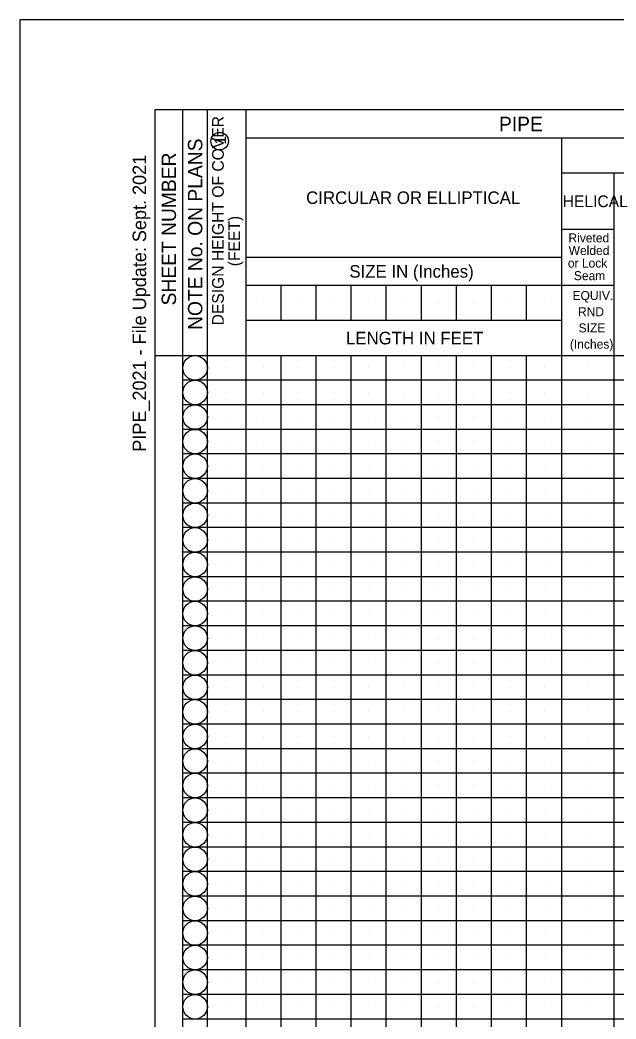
# Model space of a CAD drawing. Extents: x 0 to 1.42, y 0 to 0.92.
# Drawn here: x 0 to 0.2763, y 0.4539 to 0.9167 of the extents above; entities that cross this region are included whole.
import ezdxf

# ---------------------------------------------------------------- set-up
doc = ezdxf.new("R2010")
doc.units = 0
for name, color, linetype in [('#plot_shape', 7, 'Continuous'), ('P_ODOT_PLAN_Border', 7, 'Continuous'), ('P_ODOT_PLAN_General', 7, 'Continuous'), ('P_RDWY_PLAN_NotesTx', 7, 'Continuous')]:
    doc.layers.add(name, color=color, linetype=linetype)

msp = doc.modelspace()

# ---------------------------------------------------------------- linework, layer by layer
at = {"layer": '#plot_shape'}
msp.add_lwpolyline([(0, 0), (1.41667, 0), (1.41667, 0.91667), (0, 0.91667)], close=True, dxfattribs=at)
at = {"layer": 'P_ODOT_PLAN_Border'}
msp.add_lwpolyline([(0.0625, 0.04167), (1.39583, 0.04167), (1.39583, 0.875), (0.0625, 0.875)], close=True, dxfattribs=at)
at = {"layer": 'P_ODOT_PLAN_General'}
for p, q in [((0.07551, 0.26037), (0.07551, 0.875)), ((0.08689, 0.26037), (0.08689, 0.875)), ((0.10478, 0.26037), (0.10478, 0.875)), ((0.35681, 0.86199), (0.10478, 0.86199)), ((0.25112, 0.26037), (0.25112, 0.86199)), ((0.35681, 0.84573), (0.25112, 0.84573)), ((0.27551, 0.26037), (0.27551, 0.84573)), ((0.25112, 0.81972), (0.27551, 0.81972)), ((0.25112, 0.80671), (0.10478, 0.80671)), ((0.27551, 0.7937), (0.10478, 0.7937)), ((0.12104, 0.77744), (0.12104, 0.7937)), ((0.1373, 0.77744), (0.1373, 0.7937)), ((0.15356, 0.77744), (0.15356, 0.7937)), ((0.16982, 0.77744), (0.16982, 0.7937)), ((0.18608, 0.77744), (0.18608, 0.7937)), ((0.20234, 0.77744), (0.20234, 0.7937)), ((0.2186, 0.77744), (0.2186, 0.7937)), ((0.23486, 0.77744), (0.23486, 0.7937)), ((0.11291, 0.78557), (0.11291, 0.78557)), ((0.12917, 0.78557), (0.12917, 0.78557)), ((0.14543, 0.78557), (0.14543, 0.78557)), ((0.16169, 0.78557), (0.16169, 0.78557)), ((0.17795, 0.78557), (0.17795, 0.78557)), ((0.19421, 0.78557), (0.19421, 0.78557)), ((0.21047, 0.78557), (0.21047, 0.78557)), ((0.22673, 0.78557), (0.22673, 0.78557)), ((0.24299, 0.78557), (0.24299, 0.78557)), ((0.25112, 0.77744), (0.10478, 0.77744)), ((0.0625, 0.76118), (0.35681, 0.76118)), ((0.12104, 0.26037), (0.12104, 0.76118)), ((0.1373, 0.26037), (0.1373, 0.76118)), ((0.15356, 0.26037), (0.15356, 0.76118)), ((0.16982, 0.26037), (0.16982, 0.76118)), ((0.18608, 0.26037), (0.18608, 0.76118)), ((0.20234, 0.26037), (0.20234, 0.76118)), ((0.2186, 0.26037), (0.2186, 0.76118)), ((0.23486, 0.26037), (0.23486, 0.76118)), ((0.09583, 0.75549), (0.09583, 0.75549)), ((0.11291, 0.75549), (0.11291, 0.75549)), ((0.12917, 0.75549), (0.12917, 0.75549)), ((0.14543, 0.75549), (0.14543, 0.75549)), ((0.16176, 0.75562), (0.16176, 0.75562)), ((0.17795, 0.75549), (0.17795, 0.75549)), ((0.19421, 0.75549), (0.19421, 0.75549)), ((0.21047, 0.75549), (0.21047, 0.75549)), ((0.22673, 0.75549), (0.22673, 0.75549)), ((0.24299, 0.75549), (0.24299, 0.75549)), ((0.26331, 0.75549), (0.26331, 0.75549)), ((0.25112, 0.7498), (0.07551, 0.7498)), ((0.50965, 0.7498), (0.25112, 0.7498)), ((0.09583, 0.74411), (0.09583, 0.74411)), ((0.11291, 0.74411), (0.11291, 0.74411)), ((0.12917, 0.74411), (0.12917, 0.74411)), ((0.14543, 0.74411), (0.14543, 0.74411)), ((0.16169, 0.74411), (0.16169, 0.74411)), ((0.17795, 0.74411), (0.17795, 0.74411)), ((0.19421, 0.74411), (0.19421, 0.74411)), ((0.21047, 0.74411), (0.21047, 0.74411)), ((0.22673, 0.74411), (0.22673, 0.74411)), ((0.24299, 0.74411), (0.24299, 0.74411)), ((0.26331, 0.74411), (0.26331, 0.74411)), ((0.25112, 0.73842), (0.07551, 0.73842)), ((0.50965, 0.73842), (0.25112, 0.73842)), ((0.09583, 0.73273), (0.09583, 0.73273)), ((0.11291, 0.73273), (0.11291, 0.73273)), ((0.12917, 0.73273), (0.12917, 0.73273)), ((0.14543, 0.73273), (0.14543, 0.73273)), ((0.16169, 0.73273), (0.16169, 0.73273)), ((0.17795, 0.73273), (0.17795, 0.73273)), ((0.19421, 0.73273), (0.19421, 0.73273)), ((0.21047, 0.73273), (0.21047, 0.73273)), ((0.22673, 0.73273), (0.22673, 0.73273)), ((0.24299, 0.73273), (0.24299, 0.73273)), ((0.26331, 0.73273), (0.26331, 0.73273)), ((0.25112, 0.72703), (0.07551, 0.72703)), ((0.50965, 0.72703), (0.25112, 0.72703)), ((0.09583, 0.72134), (0.09583, 0.72134)), ((0.11291, 0.72134), (0.11291, 0.72134)), ((0.12917, 0.72134), (0.12917, 0.72134)), ((0.14543, 0.72134), (0.14543, 0.72134)), ((0.16169, 0.72134), (0.16169, 0.72134)), ((0.17795, 0.72134), (0.17795, 0.72134)), ((0.19421, 0.72134), (0.19421, 0.72134)), ((0.21047, 0.72134), (0.21047, 0.72134)), ((0.22673, 0.72134), (0.22673, 0.72134)), ((0.24299, 0.72134), (0.24299, 0.72134)), ((0.26331, 0.72134), (0.26331, 0.72134)), ((0.25112, 0.71565), (0.07551, 0.71565)), ((0.50965, 0.71565), (0.25112, 0.71565)), ((0.09583, 0.70996), (0.09583, 0.70996)), ((0.11291, 0.70996), (0.11291, 0.70996)), ((0.12917, 0.70996), (0.12917, 0.70996)), ((0.14543, 0.70996), (0.14543, 0.70996)), ((0.16169, 0.70996), (0.16169, 0.70996)), ((0.17795, 0.70996), (0.17795, 0.70996)), ((0.19421, 0.70996), (0.19421, 0.70996)), ((0.21047, 0.70996), (0.21047, 0.70996)), ((0.22673, 0.70996), (0.22673, 0.70996)), ((0.24299, 0.70996), (0.24299, 0.70996)), ((0.26331, 0.70996), (0.26331, 0.70996)), ((0.25112, 0.70427), (0.07551, 0.70427)), ((0.50965, 0.70427), (0.25112, 0.70427)), ((0.09583, 0.69858), (0.09583, 0.69858)), ((0.11291, 0.69858), (0.11291, 0.69858)), ((0.12917, 0.69858), (0.12917, 0.69858)), ((0.14543, 0.69858), (0.14543, 0.69858)), ((0.16169, 0.69858), (0.16169, 0.69858)), ((0.17795, 0.69858), (0.17795, 0.69858)), ((0.19421, 0.69858), (0.19421, 0.69858)), ((0.21047, 0.69858), (0.21047, 0.69858)), ((0.22673, 0.69858), (0.22673, 0.69858)), ((0.24299, 0.69858), (0.24299, 0.69858)), ((0.26331, 0.69858), (0.26331, 0.69858)), ((0.25112, 0.69289), (0.07551, 0.69289)), ((0.50965, 0.69289), (0.25112, 0.69289)), ((0.09583, 0.6872), (0.09583, 0.6872)), ((0.11291, 0.6872), (0.11291, 0.6872)), ((0.12917, 0.6872), (0.12917, 0.6872)), ((0.14543, 0.6872), (0.14543, 0.6872)), ((0.16169, 0.6872), (0.16169, 0.6872)), ((0.17795, 0.6872), (0.17795, 0.6872)), ((0.19421, 0.6872), (0.19421, 0.6872)), ((0.21047, 0.6872), (0.21047, 0.6872)), ((0.22673, 0.6872), (0.22673, 0.6872)), ((0.24299, 0.6872), (0.24299, 0.6872)), ((0.26331, 0.6872), (0.26331, 0.6872)), ((0.25112, 0.68151), (0.07551, 0.68151)), ((0.50965, 0.68151), (0.25112, 0.68151)), ((0.09583, 0.67582), (0.09583, 0.67582)), ((0.11291, 0.67582), (0.11291, 0.67582)), ((0.12917, 0.67582), (0.12917, 0.67582)), ((0.14543, 0.67582), (0.14543, 0.67582)), ((0.16169, 0.67582), (0.16169, 0.67582)), ((0.17795, 0.67582), (0.17795, 0.67582)), ((0.19421, 0.67582), (0.19421, 0.67582)), ((0.21047, 0.67582), (0.21047, 0.67582)), ((0.22673, 0.67582), (0.22673, 0.67582)), ((0.24299, 0.67582), (0.24299, 0.67582)), ((0.26331, 0.67582), (0.26331, 0.67582)), ((0.25112, 0.67012), (0.07551, 0.67012)), ((0.50965, 0.67012), (0.25112, 0.67012)), ((0.09583, 0.66443), (0.09583, 0.66443)), ((0.11291, 0.66443), (0.11291, 0.66443)), ((0.12917, 0.66443), (0.12917, 0.66443)), ((0.14543, 0.66443), (0.14543, 0.66443)), ((0.16169, 0.66443), (0.16169, 0.66443)), ((0.17795, 0.66443), (0.17795, 0.66443)), ((0.19421, 0.66443), (0.19421, 0.66443)), ((0.21047, 0.66443), (0.21047, 0.66443)), ((0.22673, 0.66443), (0.22673, 0.66443)), ((0.24299, 0.66443), (0.24299, 0.66443)), ((0.26331, 0.66443), (0.26331, 0.66443)), ((0.25112, 0.65874), (0.07551, 0.65874)), ((0.50965, 0.65874), (0.25112, 0.65874)), ((0.09583, 0.65305), (0.09583, 0.65305)), ((0.11291, 0.65305), (0.11291, 0.65305)), ((0.12917, 0.65305), (0.12917, 0.65305)), ((0.14543, 0.65305), (0.14543, 0.65305)), ((0.16169, 0.65305), (0.16169, 0.65305)), ((0.17795, 0.65305), (0.17795, 0.65305)), ((0.19421, 0.65305), (0.19421, 0.65305)), ((0.21047, 0.65305), (0.21047, 0.65305)), ((0.22695, 0.653), (0.22695, 0.653)), ((0.24299, 0.65305), (0.24299, 0.65305)), ((0.26331, 0.65305), (0.26331, 0.65305)), ((0.25112, 0.64736), (0.07551, 0.64736)), ((0.50965, 0.64736), (0.25112, 0.64736)), ((0.09583, 0.64167), (0.09583, 0.64167)), ((0.11291, 0.64167), (0.11291, 0.64167)), ((0.12917, 0.64167), (0.12917, 0.64167)), ((0.14543, 0.64167), (0.14543, 0.64167)), ((0.16169, 0.64167), (0.16169, 0.64167)), ((0.17795, 0.64167), (0.17795, 0.64167)), ((0.19421, 0.64167), (0.19421, 0.64167)), ((0.21047, 0.64167), (0.21047, 0.64167)), ((0.22673, 0.64167), (0.22673, 0.64167)), ((0.24364, 0.64213), (0.24364, 0.64213)), ((0.26331, 0.64167), (0.26331, 0.64167)), ((0.25112, 0.63598), (0.07551, 0.63598)), ((0.50965, 0.63598), (0.25112, 0.63598)), ((0.09583, 0.63029), (0.09583, 0.63029)), ((0.11291, 0.63029), (0.11291, 0.63029)), ((0.12917, 0.63029), (0.12917, 0.63029)), ((0.14543, 0.63029), (0.14543, 0.63029)), ((0.16169, 0.63029), (0.16169, 0.63029)), ((0.17795, 0.63029), (0.17795, 0.63029)), ((0.19421, 0.63029), (0.19421, 0.63029)), ((0.21047, 0.63029), (0.21047, 0.63029)), ((0.22673, 0.63029), (0.22673, 0.63029)), ((0.24299, 0.63029), (0.24299, 0.63029)), ((0.26331, 0.63029), (0.26331, 0.63029)), ((0.25112, 0.6246), (0.07551, 0.6246)), ((0.50965, 0.6246), (0.25112, 0.6246)), ((0.09583, 0.61891), (0.09583, 0.61891)), ((0.11291, 0.61891), (0.11291, 0.61891)), ((0.12917, 0.61891), (0.12917, 0.61891)), ((0.14543, 0.61891), (0.14543, 0.61891)), ((0.16169, 0.61891), (0.16169, 0.61891)), ((0.17795, 0.61891), (0.17795, 0.61891)), ((0.19421, 0.61891), (0.19421, 0.61891)), ((0.21047, 0.61891), (0.21047, 0.61891)), ((0.22673, 0.61891), (0.22673, 0.61891)), ((0.24299, 0.61891), (0.24299, 0.61891)), ((0.26331, 0.61891), (0.26331, 0.61891)), ((0.25112, 0.61321), (0.07551, 0.61321)), ((0.50965, 0.61321), (0.25112, 0.61321)), ((0.09583, 0.60752), (0.09583, 0.60752)), ((0.11291, 0.60752), (0.11291, 0.60752)), ((0.12917, 0.60752), (0.12917, 0.60752)), ((0.14543, 0.60752), (0.14543, 0.60752)), ((0.16169, 0.60752), (0.16169, 0.60752)), ((0.17795, 0.60752), (0.17795, 0.60752)), ((0.19421, 0.60752), (0.19421, 0.60752)), ((0.21047, 0.60752), (0.21047, 0.60752)), ((0.22673, 0.60752), (0.22673, 0.60752)), ((0.24299, 0.60752), (0.24299, 0.60752)), ((0.26331, 0.60752), (0.26331, 0.60752)), ((0.25112, 0.60183), (0.07551, 0.60183)), ((0.50965, 0.60183), (0.25112, 0.60183)), ((0.09583, 0.59614), (0.09583, 0.59614)), ((0.11291, 0.59614), (0.11291, 0.59614)), ((0.12917, 0.59614), (0.12917, 0.59614)), ((0.14543, 0.59614), (0.14543, 0.59614)), ((0.16169, 0.59614), (0.16169, 0.59614)), ((0.17795, 0.59614), (0.17795, 0.59614)), ((0.19421, 0.59614), (0.19421, 0.59614)), ((0.21047, 0.59614), (0.21047, 0.59614)), ((0.22673, 0.59614), (0.22673, 0.59614)), ((0.24299, 0.59614), (0.24299, 0.59614)), ((0.26331, 0.59614), (0.26331, 0.59614)), ((0.25112, 0.59045), (0.07551, 0.59045)), ((0.50965, 0.59045), (0.25112, 0.59045)), ((0.09583, 0.58476), (0.09583, 0.58476)), ((0.11291, 0.58476), (0.11291, 0.58476)), ((0.12917, 0.58476), (0.12917, 0.58476)), ((0.14543, 0.58476), (0.14543, 0.58476)), ((0.16169, 0.58476), (0.16169, 0.58476)), ((0.17795, 0.58476), (0.17795, 0.58476)), ((0.19421, 0.58476), (0.19421, 0.58476)), ((0.21047, 0.58476), (0.21047, 0.58476)), ((0.22673, 0.58476), (0.22673, 0.58476)), ((0.24299, 0.58476), (0.24299, 0.58476)), ((0.26331, 0.58476), (0.26331, 0.58476)), ((0.25112, 0.57907), (0.07551, 0.57907)), ((0.50965, 0.57907), (0.25112, 0.57907)), ((0.09583, 0.57338), (0.09583, 0.57338)), ((0.11291, 0.57338), (0.11291, 0.57338)), ((0.12917, 0.57338), (0.12917, 0.57338)), ((0.14543, 0.57338), (0.14543, 0.57338)), ((0.16169, 0.57338), (0.16169, 0.57338)), ((0.17795, 0.57338), (0.17795, 0.57338)), ((0.19421, 0.57338), (0.19421, 0.57338)), ((0.21047, 0.57338), (0.21047, 0.57338)), ((0.22673, 0.57338), (0.22673, 0.57338)), ((0.24299, 0.57338), (0.24299, 0.57338)), ((0.26331, 0.57338), (0.26331, 0.57338)), ((0.25112, 0.56769), (0.07551, 0.56769)), ((0.50965, 0.56769), (0.25112, 0.56769)), ((0.09583, 0.562), (0.09583, 0.562)), ((0.11291, 0.562), (0.11291, 0.562)), ((0.12917, 0.562), (0.12917, 0.562)), ((0.14543, 0.562), (0.14543, 0.562)), ((0.16169, 0.562), (0.16169, 0.562)), ((0.17795, 0.562), (0.17795, 0.562)), ((0.19421, 0.562), (0.19421, 0.562)), ((0.21047, 0.562), (0.21047, 0.562)), ((0.22673, 0.562), (0.22673, 0.562)), ((0.24299, 0.562), (0.24299, 0.562)), ((0.26331, 0.562), (0.26331, 0.562)), ((0.25112, 0.5563), (0.07551, 0.5563)), ((0.50965, 0.5563), (0.25112, 0.5563)), ((0.09583, 0.55061), (0.09583, 0.55061)), ((0.11291, 0.55061), (0.11291, 0.55061)), ((0.12917, 0.55061), (0.12917, 0.55061)), ((0.14543, 0.55061), (0.14543, 0.55061)), ((0.16169, 0.55061), (0.16169, 0.55061)), ((0.17795, 0.55061), (0.17795, 0.55061)), ((0.19421, 0.55061), (0.19421, 0.55061)), ((0.21047, 0.55061), (0.21047, 0.55061)), ((0.22673, 0.55061), (0.22673, 0.55061)), ((0.24299, 0.55061), (0.24299, 0.55061)), ((0.26331, 0.55061), (0.26331, 0.55061)), ((0.25112, 0.54492), (0.07551, 0.54492)), ((0.08689, 0.53354), (0.08689, 0.54492)), ((0.50965, 0.54492), (0.25112, 0.54492)), ((0.09583, 0.53923), (0.09583, 0.53923)), ((0.11291, 0.53923), (0.11291, 0.53923)), ((0.12917, 0.53923), (0.12917, 0.53923)), ((0.14543, 0.53923), (0.14543, 0.53923)), ((0.16169, 0.53923), (0.16169, 0.53923)), ((0.17795, 0.53923), (0.17795, 0.53923)), ((0.19421, 0.53923), (0.19421, 0.53923)), ((0.21047, 0.53923), (0.21047, 0.53923)), ((0.22673, 0.53923), (0.22673, 0.53923)), ((0.24299, 0.53923), (0.24299, 0.53923)), ((0.26331, 0.53923), (0.26331, 0.53923)), ((0.25112, 0.53354), (0.07551, 0.53354)), ((0.50965, 0.53354), (0.25112, 0.53354)), ((0.09583, 0.52785), (0.09583, 0.52785)), ((0.11291, 0.52785), (0.11291, 0.52785)), ((0.12917, 0.52785), (0.12917, 0.52785)), ((0.14543, 0.52785), (0.14543, 0.52785)), ((0.16169, 0.52785), (0.16169, 0.52785)), ((0.17795, 0.52785), (0.17795, 0.52785)), ((0.19421, 0.52785), (0.19421, 0.52785)), ((0.21047, 0.52785), (0.21047, 0.52785)), ((0.22673, 0.52785), (0.22673, 0.52785)), ((0.24299, 0.52785), (0.24299, 0.52785)), ((0.26331, 0.52785), (0.26331, 0.52785)), ((0.25112, 0.52216), (0.07551, 0.52216)), ((0.50965, 0.52216), (0.25112, 0.52216)), ((0.09583, 0.51647), (0.09583, 0.51647)), ((0.11291, 0.51647), (0.11291, 0.51647)), ((0.12917, 0.51647), (0.12917, 0.51647)), ((0.14543, 0.51647), (0.14543, 0.51647)), ((0.16169, 0.51647), (0.16169, 0.51647)), ((0.17795, 0.51647), (0.17795, 0.51647)), ((0.19421, 0.51647), (0.19421, 0.51647)), ((0.21047, 0.51647), (0.21047, 0.51647)), ((0.22673, 0.51647), (0.22673, 0.51647)), ((0.24299, 0.51647), (0.24299, 0.51647)), ((0.26331, 0.51647), (0.26331, 0.51647)), ((0.25112, 0.51078), (0.07551, 0.51078)), ((0.50965, 0.51078), (0.25112, 0.51078)), ((0.09583, 0.50509), (0.09583, 0.50509)), ((0.11291, 0.50509), (0.11291, 0.50509)), ((0.12917, 0.50509), (0.12917, 0.50509)), ((0.14543, 0.50509), (0.14543, 0.50509)), ((0.16169, 0.50509), (0.16169, 0.50509)), ((0.17795, 0.50509), (0.17795, 0.50509)), ((0.19421, 0.50509), (0.19421, 0.50509)), ((0.21047, 0.50509), (0.21047, 0.50509)), ((0.22673, 0.50509), (0.22673, 0.50509)), ((0.24299, 0.50509), (0.24299, 0.50509)), ((0.26331, 0.50509), (0.26331, 0.50509)), ((0.25112, 0.49939), (0.07551, 0.49939)), ((0.50965, 0.49939), (0.25112, 0.49939)), ((0.09583, 0.4937), (0.09583, 0.4937)), ((0.11291, 0.4937), (0.11291, 0.4937)), ((0.12917, 0.4937), (0.12917, 0.4937)), ((0.14543, 0.4937), (0.14543, 0.4937)), ((0.16169, 0.4937), (0.16169, 0.4937)), ((0.17795, 0.4937), (0.17795, 0.4937)), ((0.19421, 0.4937), (0.19421, 0.4937)), ((0.21047, 0.4937), (0.21047, 0.4937)), ((0.22673, 0.4937), (0.22673, 0.4937)), ((0.24299, 0.4937), (0.24299, 0.4937)), ((0.26331, 0.4937), (0.26331, 0.4937)), ((0.25112, 0.48801), (0.07551, 0.48801)), ((0.50965, 0.48801), (0.25112, 0.48801)), ((0.09583, 0.48232), (0.09583, 0.48232)), ((0.11291, 0.48232), (0.11291, 0.48232)), ((0.12917, 0.48232), (0.12917, 0.48232)), ((0.14543, 0.48232), (0.14543, 0.48232)), ((0.16169, 0.48232), (0.16169, 0.48232)), ((0.17795, 0.48232), (0.17795, 0.48232)), ((0.19421, 0.48232), (0.19421, 0.48232)), ((0.21047, 0.48232), (0.21047, 0.48232)), ((0.22673, 0.48232), (0.22673, 0.48232)), ((0.24299, 0.48232), (0.24299, 0.48232)), ((0.26331, 0.48232), (0.26331, 0.48232)), ((0.25112, 0.47663), (0.07551, 0.47663)), ((0.50965, 0.47663), (0.25112, 0.47663)), ((0.09583, 0.47094), (0.09583, 0.47094)), ((0.11291, 0.47094), (0.11291, 0.47094)), ((0.12917, 0.47094), (0.12917, 0.47094)), ((0.14543, 0.47094), (0.14543, 0.47094)), ((0.16169, 0.47094), (0.16169, 0.47094)), ((0.17795, 0.47094), (0.17795, 0.47094)), ((0.19421, 0.47094), (0.19421, 0.47094)), ((0.21047, 0.47094), (0.21047, 0.47094)), ((0.22673, 0.47094), (0.22673, 0.47094)), ((0.24299, 0.47094), (0.24299, 0.47094)), ((0.26331, 0.47094), (0.26331, 0.47094)), ((0.25112, 0.46525), (0.07551, 0.46525)), ((0.50965, 0.46525), (0.25112, 0.46525)), ((0.09583, 0.45956), (0.09583, 0.45956)), ((0.11291, 0.45956), (0.11291, 0.45956)), ((0.12917, 0.45956), (0.12917, 0.45956)), ((0.14543, 0.45956), (0.14543, 0.45956)), ((0.16169, 0.45956), (0.16169, 0.45956)), ((0.17795, 0.45956), (0.17795, 0.45956)), ((0.19421, 0.45956), (0.19421, 0.45956)), ((0.21047, 0.45956), (0.21047, 0.45956)), ((0.22673, 0.45956), (0.22673, 0.45956)), ((0.24299, 0.45956), (0.24299, 0.45956)), ((0.26331, 0.45956), (0.26331, 0.45956)), ((0.25112, 0.45387), (0.07551, 0.45387)), ((0.50965, 0.45387), (0.25112, 0.45387))]:
    msp.add_line(p, q, dxfattribs=at)
for centre in [(0.0812, 0.75549), (0.0812, 0.74411), (0.0812, 0.73273), (0.0812, 0.72134), (0.0812, 0.70996), (0.0812, 0.69858), (0.0812, 0.6872), (0.0812, 0.67582), (0.0812, 0.66443), (0.0812, 0.65305), (0.0812, 0.64167), (0.0812, 0.63029), (0.0812, 0.61891), (0.0812, 0.60752), (0.0812, 0.59614), (0.0812, 0.58476), (0.0812, 0.57338), (0.0812, 0.562), (0.0812, 0.55061), (0.0812, 0.53923), (0.0812, 0.52785), (0.0812, 0.51647), (0.0812, 0.50509), (0.0812, 0.4937), (0.0812, 0.48232), (0.0812, 0.47094), (0.0812, 0.45956)]:
    msp.add_circle(centre, 0.00569, dxfattribs=at)
at = {"layer": 'P_RDWY_PLAN_NotesTx'}
msp.add_circle((0.09258, 0.86053), 0.00407, dxfattribs=at)

# ---------------------------------------------------------------- texts
for s, height, p in [('DESIGN HEIGHT OF COVER', 0.0054167, (0.09448, 0.77518)), ('NOTE No. ON PLANS', 0.0066667, (0.08453, 0.77309)), ('1', 0.00542, (0.09549, 0.859)), ('PIPE_2021 - File Update: Sept. 2021', 0.00625, (0.05848, 0.71667)), ('SHEET NUMBER', 0.0066667, (0.07234, 0.78443)), ('(FEET)', 0.005417, (0.10199, 0.80258))]:
    msp.add_text(s, height=height, rotation=90, dxfattribs=at).set_placement(p)
for s, height, p in [('PIPE', 0.006667, (0.22205, 0.86516)), ('CIRCULAR OR ELLIPTICAL', 0.0058333, (0.13265, 0.83143)), ('HELICAL', 0.005417, (0.25158, 0.82997)), ('Riveted', 0.004167, (0.25425, 0.81364)), ('Welded', 0.004167, (0.25435, 0.80781)), ('or Lock', 0.004167, (0.25398, 0.80197)), ('SIZE IN (Inches)', 0.0058333, (0.15269, 0.79729)), ('Seam', 0.004167, (0.25677, 0.79614)), ('EQUIV.', 0.004167, (0.25614, 0.78692)), ('RND', 0.004167, (0.25868, 0.77942)), ('SIZE', 0.004167, (0.25896, 0.77192)), ('LENGTH IN FEET', 0.0058333, (0.1511, 0.76639)), ('(Inches)', 0.004167, (0.25493, 0.76442))]:
    msp.add_text(s, height=height, dxfattribs=at).set_placement(p)

doc.saveas('drawing.dxf')
